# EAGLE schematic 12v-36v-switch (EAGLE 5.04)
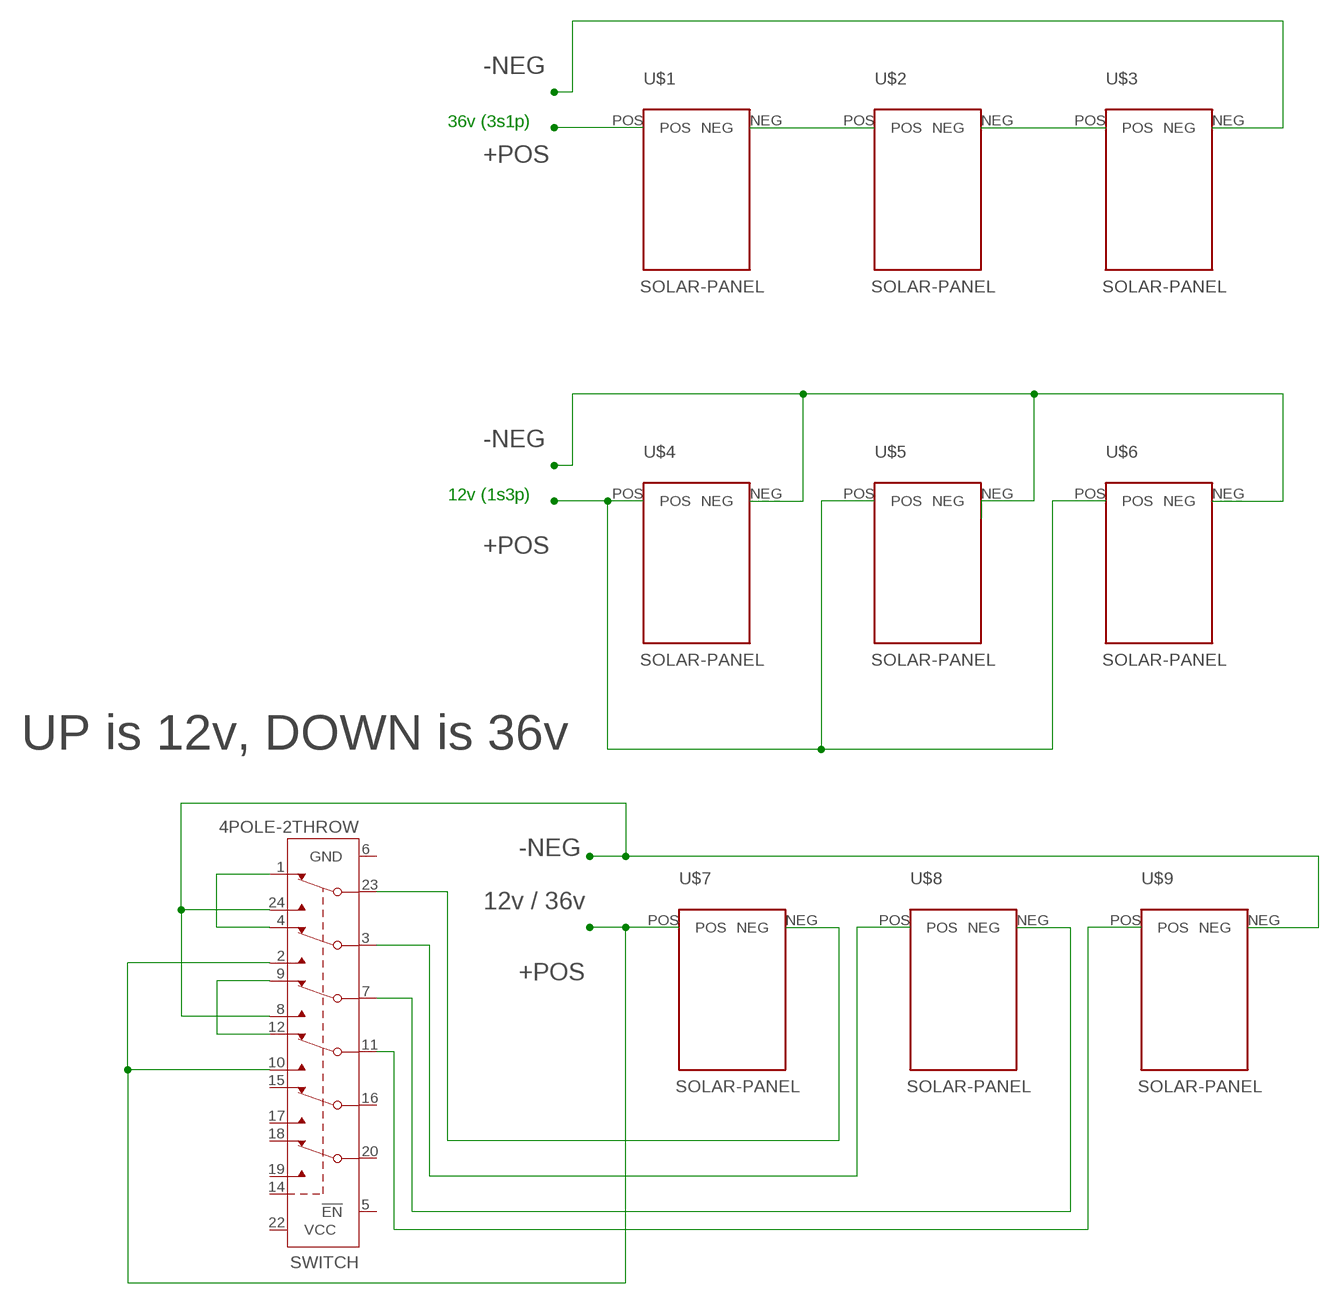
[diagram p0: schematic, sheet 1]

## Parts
SWITCH  4POLE-2THROW  MAX4948ETG  [TQFN24-EP]
U$1  SOLAR-PANEL  [SOLAR-PANEL]
U$2  SOLAR-PANEL  [SOLAR-PANEL]
U$3  SOLAR-PANEL  [SOLAR-PANEL]
U$4  SOLAR-PANEL  [SOLAR-PANEL]
U$5  SOLAR-PANEL  [SOLAR-PANEL]
U$6  SOLAR-PANEL  [SOLAR-PANEL]
U$7  SOLAR-PANEL  [SOLAR-PANEL]
U$8  SOLAR-PANEL  [SOLAR-PANEL]
U$9  SOLAR-PANEL  [SOLAR-PANEL]

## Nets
N$1: U$1.NEG U$2.POS
N$2: U$2.NEG U$3.POS
N$3: U$3.NEG
N$4: U$1.POS
N$5: SWITCH.23(COM6) U$7.NEG
N$6: U$4.POS U$5.POS U$6.POS
N$8: SWITCH.3(COM5) U$8.POS
N$9: SWITCH.7(COM4) U$8.NEG
N$10: SWITCH.2(NO5) SWITCH.10(NO3) U$7.POS
N$12: SWITCH.11(COM3) U$9.POS
N$13: SWITCH.1(NC6) SWITCH.4(NC5)
N$14: SWITCH.9(NC4) SWITCH.12(NC3)
N$15: SWITCH.8(NO4) SWITCH.24(NO6) U$9.NEG
N$16: U$4.NEG U$6.NEG
Unconnected: SWITCH.5(!EN) SWITCH.14(CB) SWITCH.15(NC2) SWITCH.16(COM2) SWITCH.17(NO2) SWITCH.18(NC1) SWITCH.19(NO1) SWITCH.20(COM1) SWITCH.EXP U$5.NEG

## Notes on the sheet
- -NEG
- 36v (3s1p)
- +POS
- -NEG
- 12v (1s3p)
- +POS
- UP is 12v, DOWN is 36v
- -NEG
- 12v / 36v
- +POS

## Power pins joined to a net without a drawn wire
GND: SWITCH.6(GND) SWITCH.21(GND)
VCC: SWITCH.22(VCC)

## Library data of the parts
SWITCH = maxim:MAX4948ETG: Hex SPDT Data Switch Source: http://datasheets.maxim-ic.com/en/ds/MAX4947-MAX4948.pdf
U$1-U$9 = trl:SOLAR-PANEL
